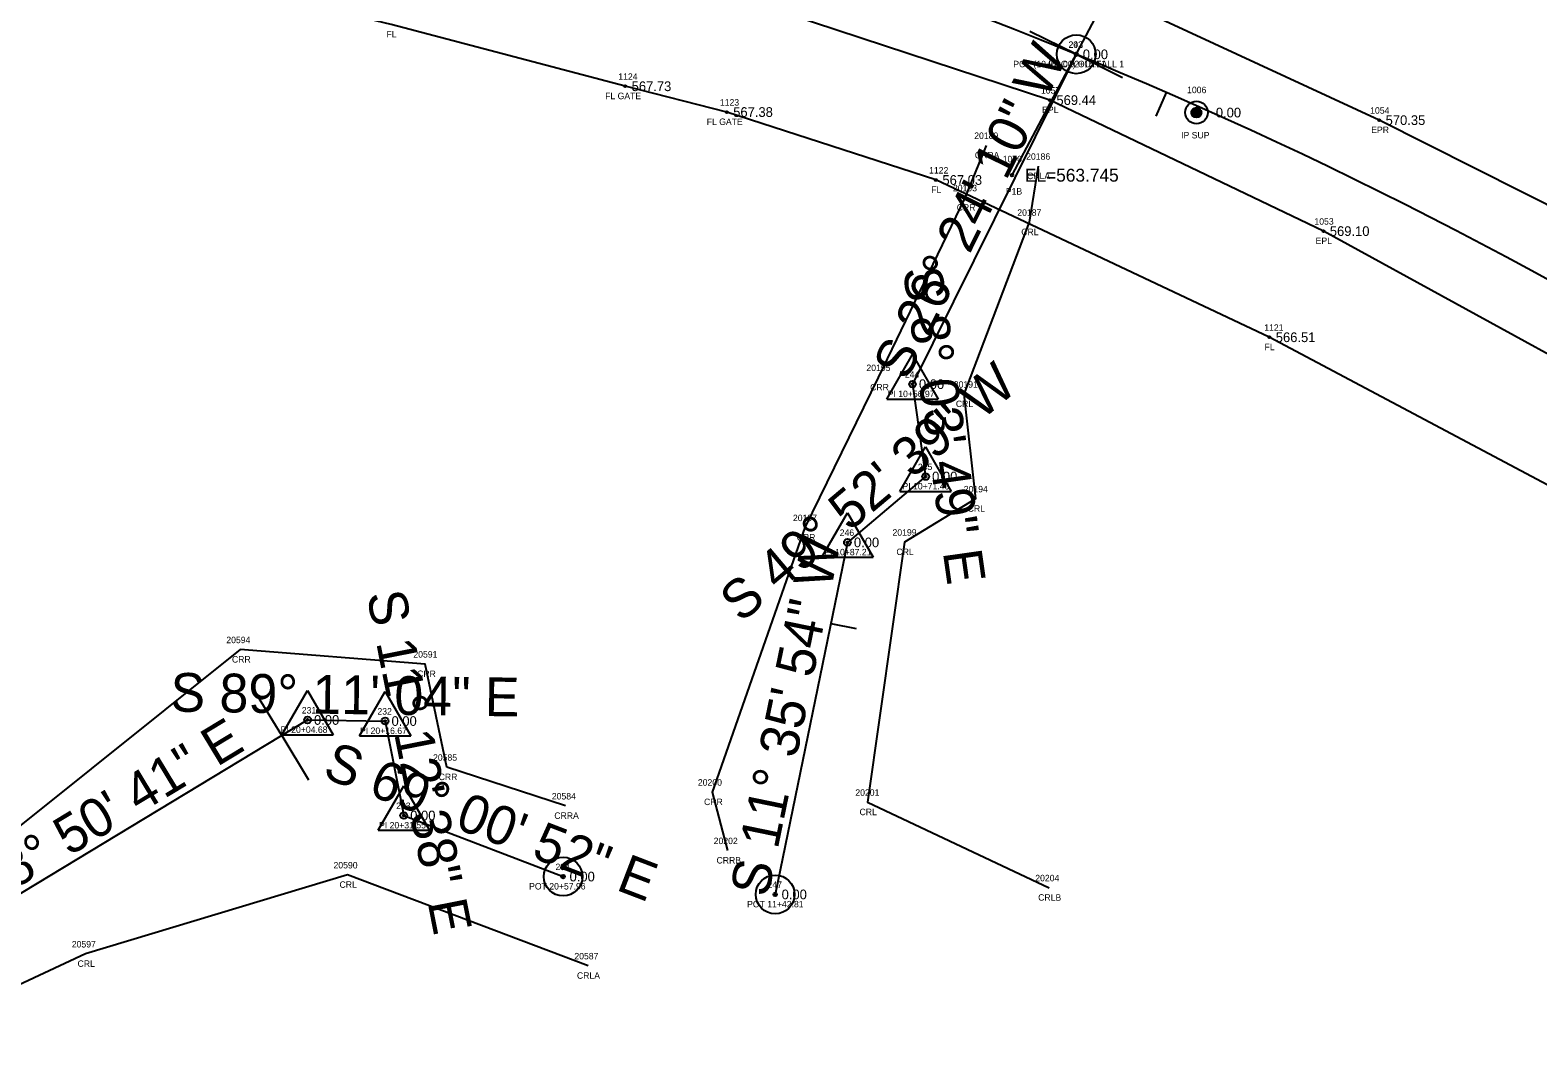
# Model space of a CAD drawing. Extents: x 1529475 to 1532053, y 876698 to 877911.
# Drawn here: x 1531265.9 to 1531499.1, y 877076.5 to 877232.8 of the extents above; entities that cross this region are included whole.
import ezdxf

# ---------------------------------------------------------------- set-up
doc = ezdxf.new("R2010")
doc.units = 0
for name, color, linetype in [('RD_EX_DR_Pipe', 7, 'Continuous'), ('RD_EX_DR_Pipe_txCode', 7, 'Continuous'), ('RD_EX_DV_Prop_txCode', 7, 'Continuous'), ('RD_EX_DV_PropPin', 7, 'Continuous'), ('RD_EX_Fence_Other', 7, 'Continuous'), ('RD_EX_Fence_Other_txCode', 7, 'Continuous'), ('RD_EX_H2O', 7, 'Continuous'), ('RD_EX_H2O_txCode', 7, 'Continuous'), ('RD_EX_Road', 7, 'Continuous'), ('RD_EX_Road_txCode', 7, 'Continuous'), ('RD_EX_TX_DV_Prop_ELEV', 7, 'Continuous'), ('RD_EX_TX_Fence_Other_ELEV', 7, 'Continuous'), ('RD_EX_TX_Road_ELEV', 7, 'Continuous'), ('RD_HC_Cl', 7, 'Continuous'), ('RD_HC_Data', 7, 'Continuous'), ('RD_HC_Data_Tic', 7, 'Continuous'), ('RD_HC_Survey_ELEV', 7, 'Continuous'), ('RD_HC_txCode', 7, 'Continuous'), ('RD_SMD_Locator', 7, 'Continuous'), ('RD_TX_Pipe_ElevEX', 7, 'Continuous')]:
    doc.layers.add(name, color=color, linetype=linetype)

msp = doc.modelspace()

# ---------------------------------------------------------------- linework, layer by layer
at = {"layer": 'RD_EX_DR_Pipe'}
msp.add_line((1531438.86, 877250.34), (1531417.78, 877210.38), dxfattribs=at)
at = {"layer": 'RD_EX_DV_PropPin'}
for p, q in [((1531445.85, 877219.46), (1531445.85, 877220.68)), ((1531445.89, 877219.44), (1531445.89, 877220.71)), ((1531445.92, 877219.42), (1531445.92, 877220.73)), ((1531445.96, 877219.4), (1531445.96, 877220.75)), ((1531445.99, 877219.38), (1531445.99, 877220.77)), ((1531446.03, 877219.37), (1531446.03, 877220.78)), ((1531446.06, 877219.35), (1531446.06, 877220.79)), ((1531446.1, 877219.34), (1531446.1, 877220.81)), ((1531446.13, 877219.33), (1531446.13, 877220.81)), ((1531446.17, 877219.33), (1531446.17, 877220.82)), ((1531446.2, 877219.32), (1531446.2, 877220.83)), ((1531446.24, 877219.32), (1531446.24, 877220.83)), ((1531446.27, 877219.31), (1531446.27, 877220.83)), ((1531446.31, 877219.31), (1531446.31, 877220.84)), ((1531446.34, 877219.31), (1531446.34, 877220.83)), ((1531446.38, 877219.32), (1531446.38, 877220.83)), ((1531446.41, 877219.32), (1531446.41, 877220.83)), ((1531446.45, 877219.33), (1531446.45, 877220.82)), ((1531446.48, 877219.33), (1531446.48, 877220.81)), ((1531446.52, 877219.34), (1531446.52, 877220.81)), ((1531446.55, 877219.35), (1531446.55, 877220.79)), ((1531446.59, 877219.37), (1531446.59, 877220.78)), ((1531446.62, 877219.38), (1531446.62, 877220.77)), ((1531446.66, 877219.4), (1531446.66, 877220.75)), ((1531446.69, 877219.42), (1531446.69, 877220.73)), ((1531446.73, 877219.44), (1531446.73, 877220.71)), ((1531446.76, 877219.46), (1531446.76, 877220.68)), ((1531445.57, 877219.88), (1531445.57, 877220.27)), ((1531445.61, 877219.78), (1531445.61, 877220.37)), ((1531445.64, 877219.7), (1531445.64, 877220.44)), ((1531445.68, 877219.65), (1531445.68, 877220.5)), ((1531445.71, 877219.6), (1531445.71, 877220.55)), ((1531445.75, 877219.56), (1531445.75, 877220.59)), ((1531445.78, 877219.52), (1531445.78, 877220.63)), ((1531445.82, 877219.49), (1531445.82, 877220.66)), ((1531446.8, 877219.49), (1531446.8, 877220.66)), ((1531446.83, 877219.52), (1531446.83, 877220.63)), ((1531446.87, 877219.56), (1531446.87, 877220.59)), ((1531446.9, 877219.6), (1531446.9, 877220.55)), ((1531446.94, 877219.65), (1531446.94, 877220.5)), ((1531446.97, 877219.7), (1531446.97, 877220.44)), ((1531447.01, 877219.78), (1531447.01, 877220.37)), ((1531447.04, 877219.88), (1531447.04, 877220.27))]:
    msp.add_line(p, q, dxfattribs=at)
for radius in [1.75, 0.761]:
    msp.add_circle((1531446.31, 877220.07), radius, dxfattribs=at)
at = {"layer": 'RD_EX_Fence_Other'}
msp.add_lwpolyline([(1531584.5, 877106.78), (1531547.82, 877137.37), (1531457.58, 877185.31), (1531406.02, 877209.64), (1531373.66, 877220.15), (1531357.95, 877224.14), (1531321.76, 877233.71), (1531272.23, 877245.59), (1531232.6, 877249.66), (1531180.73, 877254.11), (1531131.27, 877254.15), (1531075.59, 877251.89), (1531032.65, 877249.5), (1530920.26, 877239.27), (1530908.15, 877238.58)], dxfattribs=at)
at = {"layer": 'RD_EX_H2O'}
for points in [[(1531348.73, 877112.8), (1531330.35, 877118.79), (1531327.02, 877134.75), (1531298.38, 877136.98), (1531263.7, 877109.21), (1531249.44, 877098.17), (1531237.97, 877099.69), (1531227.95, 877107.18), (1531213.47, 877126.62), (1531190.85, 877137.63), (1531178.72, 877139.79), (1531157.55, 877153.22), (1531117.73, 877159.68), (1531079.2, 877144.08), (1531065.91, 877145.46), (1531049.8, 877164.02), (1531030.35, 877191.82), (1530971.87, 877223.83)], [(1531413.77, 877214.99), (1531410.49, 877206.89), (1531397.09, 877179.08), (1531385.73, 877155.86), (1531371.4, 877114.93), (1531373.8, 877105.89)], [(1531421.83, 877211.77), (1531420.44, 877203.1), (1531410.33, 877176.51), (1531412.16, 877160.31), (1531401.14, 877153.61), (1531395.42, 877113.37), (1531423.53, 877100.14)], [(1531352.2, 877088.06), (1531314.99, 877102.13), (1531274.47, 877089.9), (1531245.67, 877076.46), (1531215.61, 877089.16), (1531183.19, 877108.46), (1531131.31, 877133.17), (1531102.07, 877130.33), (1531078.17, 877119.78), (1531028.38, 877147.46), (1530991.55, 877179.5)]]:
    msp.add_lwpolyline(points, dxfattribs=at)
at = {"layer": 'RD_EX_Road'}
for points in [[(1531606.64, 877133.84), (1531579.15, 877155.05), (1531564.87, 877165.27), (1531535.22, 877186.03), (1531511.53, 877200.27), (1531474.57, 877218.9), (1531430.45, 877239.35), (1531404.48, 877249.38), (1531382.32, 877256.43), (1531333.23, 877270.71), (1531303.67, 877277.44), (1531276.52, 877282.71), (1531237.32, 877287.2), (1531185.8, 877290.94), (1531132.61, 877292.77), (1531081.11, 877292.38), (1531038.69, 877288.67), (1530976.42, 877285.45), (1530941.06, 877284.26)], [(1531595.27, 877120.27), (1531553.56, 877149.9), (1531509.97, 877177.57), (1531465.94, 877201.73), (1531423.65, 877222), (1531376.09, 877237.68), (1531328.84, 877252.31), (1531282.81, 877261.85), (1531235.7, 877268.49), (1531185.47, 877272.84), (1531132.72, 877273.12), (1531080.2, 877271.87), (1531029.21, 877269.53), (1530978.47, 877268.32), (1530945.95, 877265.93), (1530941.45, 877262.44)]]:
    msp.add_lwpolyline(points, dxfattribs=at)
at = {"layer": 'RD_HC_Cl'}
for p, q in [((1531427.73, 877229.08), (1531402.39, 877178.05)), ((1531402.39, 877178.05), (1531404.42, 877163.76)), ((1531404.42, 877163.76), (1531392.33, 877153.57)), ((1531392.33, 877153.57), (1531381.15, 877099.11)), ((1531245.67, 877087.92), (1531308.82, 877126.1)), ((1531308.82, 877126.1), (1531320.81, 877125.93)), ((1531320.81, 877125.93), (1531323.7, 877111.32)), ((1531323.7, 877111.32), (1531348.35, 877101.87))]:
    msp.add_line(p, q, dxfattribs=at)
msp.add_arc((1531152.26, 876558.44), 725, 47.4237, 92.33207, dxfattribs=at)
at = {"layer": 'RD_HC_Data'}
for p, q in [((1531398.42, 877175.75), (1531402.39, 877182.63)), ((1531402.39, 877182.63), (1531406.36, 877175.75)), ((1531398.42, 877175.75), (1531406.36, 877175.75)), ((1531400.44, 877161.47), (1531404.42, 877168.35)), ((1531404.42, 877168.35), (1531408.39, 877161.47)), ((1531400.44, 877161.47), (1531408.39, 877161.47)), ((1531388.36, 877151.28), (1531392.33, 877158.16)), ((1531392.33, 877158.16), (1531396.3, 877151.28)), ((1531388.36, 877151.28), (1531396.3, 877151.28)), ((1531304.85, 877123.8), (1531308.82, 877130.68)), ((1531308.82, 877130.68), (1531312.79, 877123.8)), ((1531316.84, 877123.63), (1531320.81, 877130.51)), ((1531320.81, 877130.51), (1531324.78, 877123.63)), ((1531304.85, 877123.8), (1531312.79, 877123.8)), ((1531316.84, 877123.63), (1531324.78, 877123.63)), ((1531319.73, 877109.03), (1531323.7, 877115.91)), ((1531323.7, 877115.91), (1531327.67, 877109.03)), ((1531319.73, 877109.03), (1531327.67, 877109.03))]:
    msp.add_line(p, q, dxfattribs=at)
for centre, radius in [((1531427.73, 877229.08), 3), ((1531427.73, 877229.08), 3), ((1531427.73, 877229.08), 0.282), ((1531427.73, 877229.08), 0.282), ((1531402.39, 877178.05), 0.529), ((1531404.42, 877163.76), 0.529), ((1531392.33, 877153.57), 0.529), ((1531308.82, 877126.1), 0.529), ((1531320.81, 877125.93), 0.529), ((1531323.7, 877111.32), 0.529), ((1531348.35, 877101.87), 3), ((1531348.35, 877101.87), 0.282), ((1531381.15, 877099.11), 3), ((1531381.15, 877099.11), 0.282)]:
    msp.add_circle(centre, radius, dxfattribs=at)
at = {"layer": 'RD_HC_Data_Tic'}
for p, q in [((1531427.73, 877229.08), (1531420.56, 877232.63)), ((1531427.73, 877229.08), (1531434.89, 877225.52)), ((1531441.64, 877223.19), (1531440.05, 877219.52)), ((1531389.76, 877141.04), (1531393.68, 877140.24)), ((1531304.82, 877123.68), (1531300.68, 877130.52)), ((1531304.82, 877123.68), (1531308.96, 877116.83))]:
    msp.add_line(p, q, dxfattribs=at)
at = {"layer": 'RD_SMD_Locator'}
for centre, radius in [((1531427.73, 877229.08), 0.15), ((1531427.73, 877229.08), 0.15), ((1531357.95, 877224.14), 0.15), ((1531423.65, 877222), 0.15), ((1531373.66, 877220.15), 0.15), ((1531446.31, 877220.07), 0.15), ((1531474.57, 877218.9), 0.15), ((1531406.02, 877209.64), 0.15), ((1531417.78, 877210.38), 0.2), ((1531465.94, 877201.73), 0.15), ((1531457.58, 877185.31), 0.15), ((1531402.39, 877178.05), 0.15), ((1531404.42, 877163.76), 0.15), ((1531392.33, 877153.57), 0.15), ((1531308.82, 877126.1), 0.15), ((1531320.81, 877125.93), 0.15), ((1531323.7, 877111.32), 0.15), ((1531348.35, 877101.87), 0.15), ((1531381.15, 877099.11), 0.15)]:
    msp.add_circle(centre, radius, dxfattribs=at)

# ---------------------------------------------------------------- texts
at = {"layer": 'RD_EX_DR_Pipe_txCode'}
for s, p in [('1070', (1531416.35, 877212.38)), ('P1B', (1531416.83, 877207.38))]:
    msp.add_text(s, height=1, dxfattribs=at).set_placement(p)
at = {"layer": 'RD_EX_DV_Prop_txCode'}
for s, p in [('1006', (1531444.86, 877223.07)), ('IP SUP', (1531443.94, 877216.07))]:
    msp.add_text(s, height=1, dxfattribs=at).set_placement(p)
at = {"layer": 'RD_EX_Fence_Other_txCode'}
for s, p in [('FL', (1531321.03, 877231.71)), ('1124', (1531356.89, 877225.14)), ('FL GATE', (1531354.85, 877222.14)), ('1123', (1531372.6, 877221.15)), ('FL GATE', (1531370.56, 877218.15)), ('1122', (1531404.96, 877210.64)), ('FL', (1531405.29, 877207.64)), ('1121', (1531456.8, 877186.31)), ('FL', (1531456.84, 877183.31))]:
    msp.add_text(s, height=1, dxfattribs=at).set_placement(p)
at = {"layer": 'RD_EX_H2O_txCode'}
for s, p in [('20189', (1531411.94, 877215.99)), ('CRRA', (1531412.03, 877212.99)), ('20186', (1531419.97, 877212.77)), ('CRLA', (1531420.11, 877209.77)), ('20193', (1531408.65, 877207.89)), ('CRR', (1531409.23, 877204.89)), ('20187', (1531418.6, 877204.1)), ('CRL', (1531419.21, 877201.1)), ('20195', (1531395.26, 877180.08)), ('CRR', (1531395.84, 877177.08)), ('20191', (1531408.78, 877177.51)), ('CRL', (1531409.1, 877174.51)), ('20194', (1531410.32, 877161.31)), ('20197', (1531383.9, 877156.86)), ('CRL', (1531410.93, 877158.31)), ('20199', (1531399.3, 877154.61)), ('CRR', (1531384.48, 877153.86)), ('CRL', (1531399.91, 877151.61)), ('20594', (1531296.26, 877137.98)), ('20591', (1531325.19, 877135.75)), ('CRR', (1531297.13, 877134.98)), ('CRR', (1531325.77, 877132.75)), ('20585', (1531328.23, 877119.79)), ('CRR', (1531329.1, 877116.79)), ('20200', (1531369.2, 877115.93)), ('20584', (1531346.61, 877113.8)), ('CRR', (1531370.15, 877112.93)), ('20201', (1531393.55, 877114.37)), ('CRRA', (1531346.99, 877110.8)), ('CRL', (1531394.2, 877111.37)), ('20202', (1531371.64, 877106.89)), ('20590', (1531312.84, 877103.13)), ('CRRB', (1531372.08, 877103.89)), ('20204', (1531421.38, 877101.14)), ('CRL', (1531313.77, 877100.13)), ('CRLB', (1531421.83, 877098.14)), ('20597', (1531272.36, 877090.9)), ('CRL', (1531273.25, 877087.9)), ('20587', (1531350.09, 877089.06)), ('CRLA', (1531350.49, 877086.06))]:
    msp.add_text(s, height=1, dxfattribs=at).set_placement(p)
at = {"layer": 'RD_EX_Road_txCode'}
for s, p in [('1057', (1531422.26, 877223)), ('EPL', (1531422.44, 877220)), ('1054', (1531473.18, 877219.9)), ('EPR', (1531473.34, 877216.9)), ('1053', (1531464.56, 877202.73)), ('EPL', (1531464.74, 877199.73))]:
    msp.add_text(s, height=1, dxfattribs=at).set_placement(p)
at = {"layer": 'RD_EX_TX_DV_Prop_ELEV'}
msp.add_text('0.00', height=1.5, dxfattribs=at).set_placement((1531449.31, 877219.32))
at = {"layer": 'RD_EX_TX_Fence_Other_ELEV'}
for s, p in [('567.73', (1531358.95, 877223.39)), ('567.38', (1531374.66, 877219.4)), ('567.03', (1531407.02, 877208.89)), ('566.51', (1531458.58, 877184.56))]:
    msp.add_text(s, height=1.5, dxfattribs=at).set_placement(p)
at = {"layer": 'RD_EX_TX_Road_ELEV'}
for s, p in [('569.44', (1531424.65, 877221.25)), ('570.35', (1531475.57, 877218.15)), ('569.10', (1531466.94, 877200.98))]:
    msp.add_text(s, height=1.5, dxfattribs=at).set_placement(p)
at = {"layer": 'RD_HC_Data'}
for s, rotation, p in [('S 26%%d 24\' 10" W', 63.5971, (1531401.45, 877178.4)), ('S 8%%d 03\' 49" E', 278.0636, (1531400.88, 877195.83)), ('S 49%%d 52\' 39" W', 40.1226, (1531375.87, 877141.01)), ('S 11%%d 35\' 54" W', 78.4017, (1531380.01, 877098.54)), ('S 11%%d 12\' 38" E', 281.2106, (1531317.94, 877145.54)), ('S 89%%d 11\' 04" E', 359.1845, (1531287.59, 877127.4)), ('N 58%%d 50\' 41" E', 31.1552, (1531252.79, 877093.39)), ('S 69%%d 00\' 52" E', 339.0144, (1531310.95, 877117.29))]:
    msp.add_text(s, height=6, rotation=rotation, dxfattribs=at).set_placement(p)
at = {"layer": 'RD_HC_Survey_ELEV'}
for p in [(1531428.73, 877228.33), (1531428.73, 877228.33), (1531403.39, 877177.3), (1531405.42, 877163.01), (1531393.33, 877152.82), (1531309.82, 877125.35), (1531321.81, 877125.18), (1531324.7, 877110.57), (1531349.35, 877101.12), (1531382.15, 877098.36)]:
    msp.add_text('0.00', height=1.5, dxfattribs=at).set_placement(p)
at = {"layer": 'RD_HC_txCode'}
for s, p in [('202', (1531426.51, 877230.08)), ('243', (1531426.54, 877230.08)), ('POT (10+00.00) OUTFALL 1', (1531417.98, 877227.08)), ('POC 92+15.11', (1531423.41, 877227.08)), ('244', (1531401.21, 877179.05)), ('PI 10+56.97', (1531398.55, 877176.05)), ('245', (1531403.23, 877164.76)), ('PI 10+71.40', (1531400.84, 877161.76)), ('246', (1531391.13, 877154.57)), ('PI 10+87.21', (1531388.8, 877151.57)), ('231', (1531307.93, 877127.1)), ('232', (1531319.63, 877126.93)), ('PI 20+04.68', (1531304.66, 877124.1)), ('PI 20+16.67', (1531316.94, 877123.93)), ('233', (1531322.52, 877112.32)), ('PI 20+31.55', (1531319.88, 877109.32)), ('234', (1531347.17, 877102.87)), ('POT 20+57.96', (1531343.09, 877099.87)), ('247', (1531379.97, 877100.11)), ('POT 11+42.81', (1531376.81, 877097.11))]:
    msp.add_text(s, height=1, dxfattribs=at).set_placement(p)
at = {"layer": 'RD_TX_Pipe_ElevEX'}
msp.add_text('EL=563.745', height=2, dxfattribs=at).set_placement((1531419.78, 877209.38))

doc.saveas('drawing.dxf')
